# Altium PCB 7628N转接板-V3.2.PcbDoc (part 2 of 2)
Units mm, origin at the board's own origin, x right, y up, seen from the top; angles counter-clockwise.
Board outline 53 x 34 mm, 2 copper layers (Top, Bottom), stack 1.981 mm thick; 6 components, 131 nets, 219 pads, 60 vias.
Unrouted connection lines stored in the file: 5.
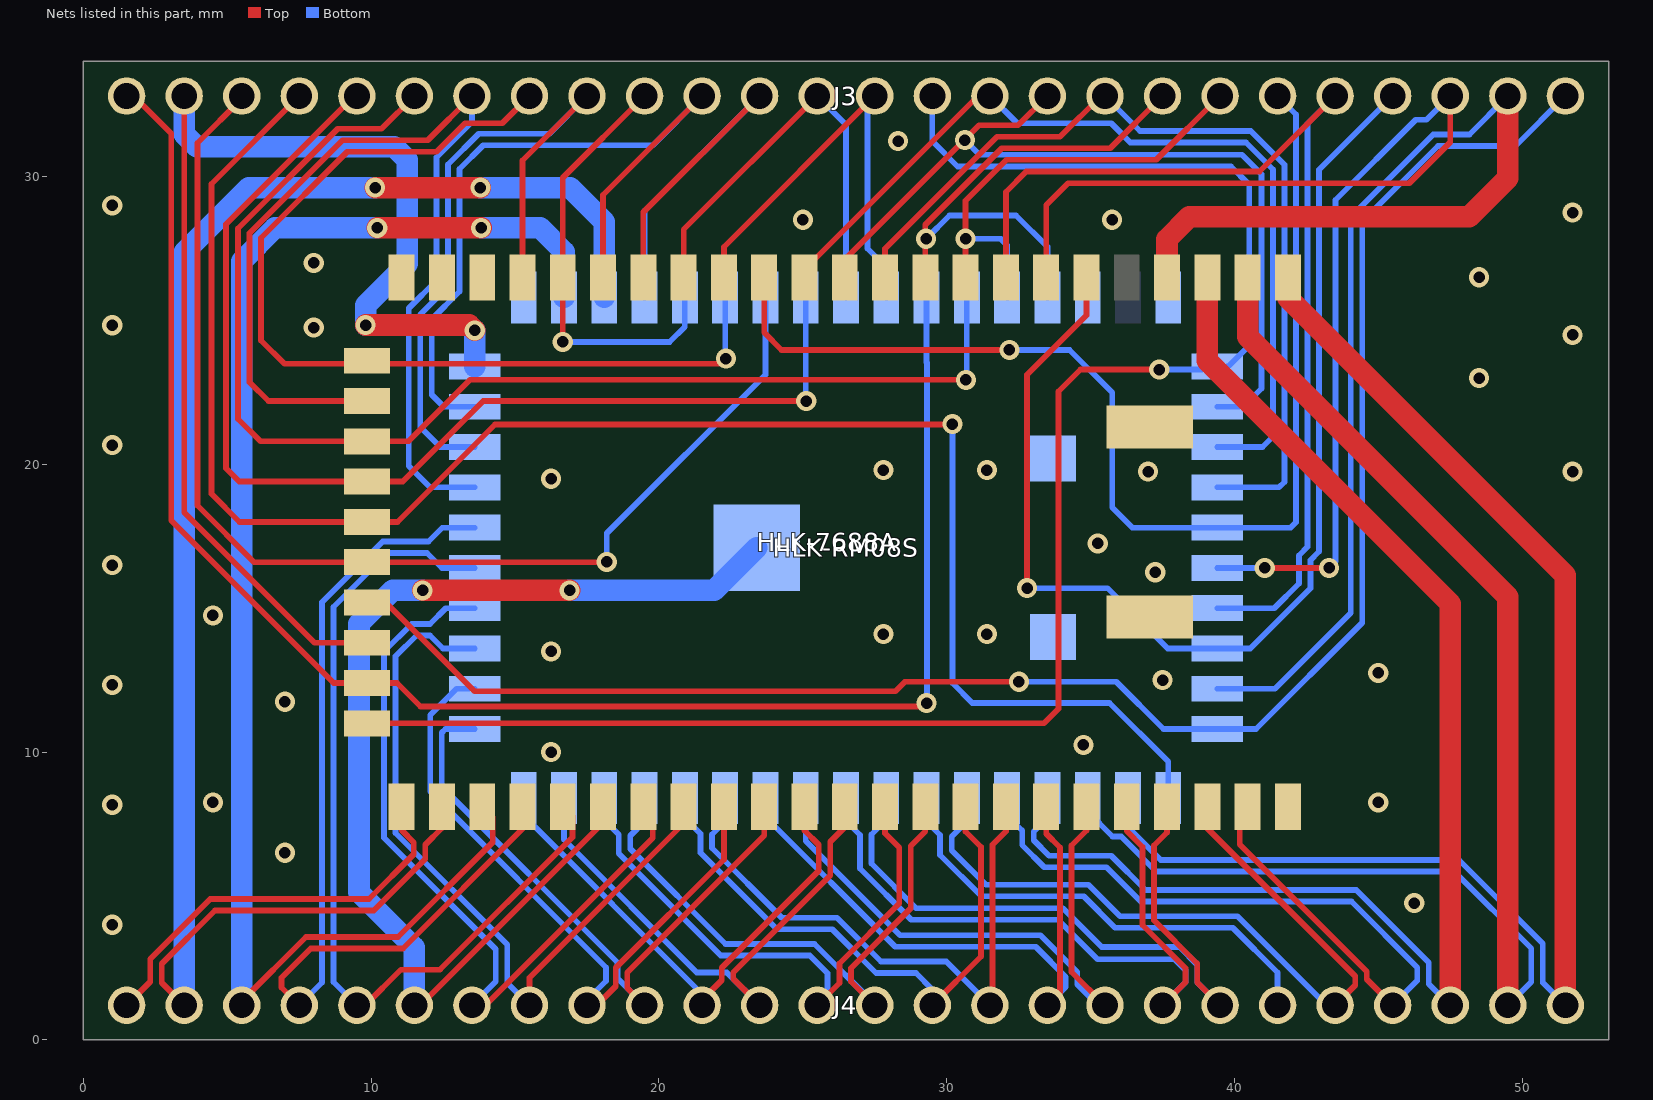
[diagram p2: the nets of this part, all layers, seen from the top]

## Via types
v1: diameter 0.7, hole 0.4, Top to Bottom, tented both sides, 59 vias
v2: diameter 0.7, hole 0.4, Top to Bottom, 1 vias

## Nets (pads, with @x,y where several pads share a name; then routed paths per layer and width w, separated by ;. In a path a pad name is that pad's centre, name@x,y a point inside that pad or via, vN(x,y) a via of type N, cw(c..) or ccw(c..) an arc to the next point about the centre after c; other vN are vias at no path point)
3.3VD: HLK-7688A.2 HLK-7688A.3 HLK-RM08S.39 HLK-RM08S.40 J4.24 J4.25 | length 142.1
  Top w0.75: v1(10.135,29.616) v1(13.792,29.616) ; v1(10.211,28.219) v1(13.818,28.219) ; HLK-7688A.3@39.057,26.499 39.057,23.605 47.5,15.162 J4.24@47.5,1.2 ; HLK-7688A.2@40.457,26.499 40.457,24.44 49.5,15.397 J4.25@49.5,1.2
  Bottom w0.75: J4.25@3.5,1.2 3.5,27.376 5.74,29.616 v1(10.135,29.616) ; J4.24@5.5,1.2 5.5,27.065 6.655,28.219 v1(10.211,28.219) ; v1(13.792,29.616) 16.916,29.616 18.1,28.433 HLK-RM08S.40@18.1,25.8 ; v1(13.818,28.219) 15.875,28.219 16.7,27.394 HLK-RM08S.39@16.7,25.8
$$$1: HLK-7688A.37 HLK-RM08S.15 J4.4 | length 31.5
  Top w0.2: J4.4@7.5,1.2 6.883,1.817 6.883,2.159 7.899,3.175 11.1,3.175 15.257,7.332 HLK-7688A.37@15.257,8.099
  Bottom w0.2: HLK-RM08S.15@32.1,8.4 32.1,7.8 32.621,7.278 32.621,6.77 33.392,6 35.551,6 36.742,4.809 44.064,4.809 46.356,2.516 46.356,2.056 J4.4@45.5,1.2
$$$2: HLK-7688A.36 HLK-RM08S.14 J4.3 | length 31.5
  Top w0.2: J4.3@5.5,1.2 5.5,1.341 7.734,3.575 10.934,3.575 14.224,6.865 14.224,7.732 HLK-7688A.36@13.857,8.099
  Bottom w0.2: HLK-RM08S.14@33.5,8.4 33.5,7.719 33.021,7.241 33.021,6.936 33.557,6.4 35.716,6.4 36.908,5.209 44.23,5.209 46.756,2.682 46.756,1.944 J4.3@47.5,1.2
AGND: HLK-7688A.57 HLK-7688A.58 HLK-RM08S.55 HLK-RM08S.56
  other v1: 1,4 46.25,4.75 7,6.5 1,8.167 4.5,8.25 45,8.25 16.25,10 34.75,10.25 7,11.75 1,12.333 37.5,12.5 45,12.75 16.25,13.5 27.8,14.1 31.4,14.1 4.5,14.75 37.25,16.25 1,16.5 35.25,17.25 16.25,19.5 37,19.75 51.75,19.75 27.8,19.8 31.4,19.8 1,20.667 48.5,23 51.75,24.5 8,24.75 1,24.833 48.5,26.5 8,27 25,28.5 35.75,28.5 51.75,28.75 1,29 28.308,31.234
ALARM_IN: HLK-7688A.13 HLK-RM08S.36 J3.16 | length 28.6
  Top w0.2: HLK-7688A.13@25.057,26.499 25.057,26.774 31.083,32.8 J3.16@31.5,32.8
  Bottom w0.2: HLK-RM08S.36@13.6,22 12.522,22 12.104,22.417 12.104,25.045 13.068,26.008 13.068,30.264 13.895,31.091 19.791,31.091 J3.16@21.5,32.8
ALARM_OUT: HLK-7688A.43 HLK-RM08S.21 J4.10 | length 23.8
  Top w0.2: J4.10@19.5,1.2 18.898,1.802 18.898,2.337 23.657,7.096 HLK-7688A.43@23.657,8.099
  Bottom w0.2: HLK-RM08S.21@23.7,8.4 23.7,7.748 28.214,3.234 33.091,3.234 34.139,2.186 34.139,1.839 J4.10@33.5,1.2
AMCLK: HLK-7688A.6 HLK-RM08S.48 J3.23 | length 25.9
  Top w0.2: 32.791,15.697 32.791,23.114 34.857,25.18 HLK-7688A.6@34.857,26.499
  Bottom w0.2: HLK-RM08S.48@29.3,25.8 29.3,23.546 29.312,23.534 29.312,11.612
ANT: HLK-7688A.22
CLK_N: 
CLK_P: 
CLKN: 
CLKP: 
CPURST_N: HLK-7688A.14 HLK-RM08S.49 J3.21 | length 13.6
  Top w0.2: HLK-7688A.14@23.657,26.499 23.657,24.578 24.257,23.978 v1(32.182,23.978)
  Bottom w0.2: 30.7,22.902 HLK-RM08S.49@30.7,25.8
DDR_BA0: 
DDR_BA1: 
DDR_BA2: 
DDR_CASN: 
DDR_CSN: 
DDR_IO_1V8_MT7688: 
DDR_MCKE: 
DDR_MDQM0: 
DDR_MDQM1: 
DDR_MDQS0: 
DDR_MDQS1: 
DDR_MODT: 
DDR_RASN: 
DDR_VREF: 
DDR_WEN: 
DEFKEY: HLK-7688A.16 HLK-RM08S.47 J3.13 | length 15.6
  Top w0.2: HLK-7688A.16@20.857,26.499 20.857,28.157 J3.13@25.5,32.8
  Bottom w0.2: J3.13@27.5,32.8 27.25,32.55 27.25,27.5 27.9,26.85 HLK-RM08S.47@27.9,25.8
GND: HLK-7688A.1 HLK-7688A.4 HLK-7688A.21 HLK-7688A.23 HLK-7688A.56 HLK-RM08S.37 HLK-RM08S.38 HLK-RM08S.52 HLK-RM08S.54 HLK-RM08S.57 J3.25 J4.21 J4.26 | length 96.1
  Top w0.75: v1(9.804,24.841) 13.411,24.841 v1(13.6,24.652) ; v1(11.786,15.621) v1(16.891,15.621) ; HLK-7688A.4@37.657,26.499 37.657,27.827 38.43,28.6 48.158,28.6 49.5,29.942 J3.25@49.5,32.8 ; HLK-7688A.1@41.857,26.499 41.857,25.783 51.5,16.14 J4.26@51.5,1.2
  Bottom w0.75: J3.25@3.5,32.8 3.5,31.476 3.937,31.039 10.795,31.039 11.252,30.582 11.252,26.975 9.804,25.527 v1(9.804,24.841) ; J4.21@11.5,1.2 11.5,3.207 9.576,5.131 9.576,14.453 10.744,15.621 v1(11.786,15.621) ; HLK-RM08S.37@13.6,23.4 v1(13.6,24.652) ; v1(16.891,15.621) 21.921,15.621 HLK-RM08S.57@23.4,17.1
HOLD: 
I2C_CLK: HLK-7688A.24 HLK-RM08S.51 J3.8 | length 38.2
  Top w0.2: J3.8@15.5,32.8 14.55,31.85 13.257,31.85 12.268,30.861 9.169,30.861 6.172,27.864 6.172,24.308 6.982,23.498 9.857,23.498 22.327,23.498 v1@22.355,23.498
  Bottom w0.2: 29.286,27.838 30.099,28.651 32.41,28.651 33.5,27.562 HLK-RM08S.51@33.5,25.8
  other v1: 22.327,23.673
I2C_DAT: HLK-7688A.25 HLK-RM08S.50 J3.7 | length 22.6
  Top w0.2: HLK-7688A.25@9.857,22.199 6.426,22.199 5.772,22.854 5.772,28.029 9.004,31.261 11.961,31.261 J3.7@13.5,32.8
  Bottom w0.2: 30.657,27.838 31.877,27.838 32.1,27.615 HLK-RM08S.50@32.1,25.8
I2S_CLK: HLK-7688A.20 HLK-RM08S.4 J3.9 | length 27.9
  Top w0.2: HLK-7688A.20@15.257,26.499 15.257,30.557 J3.9@17.5,32.8
  Bottom w0.2: J3.9@35.5,32.8 36.714,31.586 40.566,31.586 41.74,30.413 41.74,19.388 41.552,19.2 HLK-RM08S.4@39.4,19.2
I2S_SDI: HLK-7688A.17 HLK-RM08S.1 J3.12 | length 28.2
  Top w0.2: HLK-7688A.17@19.457,26.499 19.457,28.757 J3.12@23.5,32.8
  Bottom w0.2: J3.12@29.5,32.8 29.5,31.234 30.38,30.355 39.879,30.355 40.514,29.72 40.514,24.132 39.783,23.4 HLK-RM08S.1@39.4,23.4
I2S_SDO: HLK-7688A.18 HLK-RM08S.3 J3.11 | length 30
  Top w0.2: HLK-7688A.18@18.057,26.499 18.057,29.357 J3.11@21.5,32.8
  Bottom w0.2: J3.11@31.5,32.8 32.45,31.85 35.717,31.85 36.381,31.186 40.401,31.186 41.34,30.247 41.34,20.97 40.971,20.6 HLK-RM08S.3@39.4,20.6
I2S_WS: HLK-7688A.19 HLK-RM08S.2 J3.10 | length 29.8
  Top w0.2: v1(16.657,24.252) HLK-7688A.19@16.657,26.499 16.657,29.957 J3.10@19.5,32.8
  Bottom w0.2: v2(30.632,31.267) 31.139,30.761 40.26,30.761 40.94,30.081 40.94,22.633 40.307,22 HLK-RM08S.2@39.4,22
MADDR0: 
MADDR1: 
MADDR2: 
MADDR3: 
MADDR4: 
MADDR5: 
MADDR6: 
MADDR7: 
MADDR8: 
MADDR9: 
MADDR10: 
MADDR11: 
MADDR12: 
MADDR13: 
MDATA0: 
MDATA1: 
MDATA2: 
MDATA3: 
MDATA4: 
MDATA5: 
MDATA6: 
MDATA7: 
MDATA8: 
MDATA9: 
MDATA10: 
MDATA11: 
MDATA12: 
MDATA13: 
MDATA14: 
MDATA15: 
MOTO_D0: HLK-7688A.45 HLK-RM08S.23 J4.12 | length 21.6
  Top w0.2: J4.12@23.5,1.2 22.581,2.119 22.581,2.337 25.952,5.709 25.952,6.883 26.457,7.388 HLK-7688A.45@26.457,8.099
  Bottom w0.2: HLK-RM08S.23@20.9,8.4 20.9,7.71 21.445,7.164 21.445,6.498 24.1,3.843 26.023,3.843 27.547,2.319 28.932,2.319 29.5,1.751 J4.12@29.5,1.2
MOTO_D1: HLK-7688A.39 HLK-RM08S.17 J4.6 | length 26.5
  Top w0.2: J4.6@11.5,1.2 11.716,1.2 18.057,7.541 HLK-7688A.39@18.057,8.099
  Bottom w0.2: HLK-RM08S.17@29.3,8.4 29.3,7.584 29.77,7.114 29.77,6.421 31.205,4.986 34.761,4.986 35.853,3.894 39.942,3.894 41.5,2.337 J4.6@41.5,1.2
MOTO_D2: HLK-7688A.30 HLK-RM08S.11 J3.26 | length 43.2
  Top w0.2: HLK-7688A.30@9.857,15.199 10.505,15.199 13.589,12.116 28.216,12.116 28.546,12.446 v1(32.512,12.446) ; v1@32.512,12.344 v1@32.715,12.344
  Bottom w0.2: 30.2,21.4 30.2,12.4 30.891,11.709 35.662,11.709 37.7,9.671 HLK-RM08S.11@37.7,8.4
MOTO_D3: HLK-7688A.42 HLK-RM08S.20 J4.9 | length 23.6
  Top w0.2: J4.9@17.5,1.2 17.837,1.2 18.498,1.861 18.498,2.502 22.257,6.262 HLK-7688A.42@22.257,8.099
  Bottom w0.2: HLK-RM08S.20@25.1,8.4 25.1,6.914 28.38,3.634 33.257,3.634 34.539,2.352 34.539,1.924 35.263,1.2 J4.9@35.5,1.2
MOTO_D4: HLK-7688A.44 HLK-RM08S.22 J4.11 | length 22.6
  Top w0.2: J4.11@21.5,1.2 21.5,1.39 22.181,2.071 22.181,2.502 25.552,5.874 25.552,6.782 25.057,7.277 HLK-7688A.44@25.057,8.099
  Bottom w0.2: HLK-RM08S.22@22.3,8.4 22.3,7.594 21.845,7.139 21.845,6.663 24.265,4.243 26.189,4.243 27.713,2.719 29.981,2.719 J4.11@31.5,1.2
MOTO_D5: HLK-7688A.8 HLK-RM08S.45 J3.22 | length 19.4
  Top w0.2: HLK-7688A.8@32.057,26.499 32.057,29.466 32.766,30.175 40.875,30.175 J3.22@43.5,32.8
  Bottom w0.2: HLK-RM08S.45@25.1,25.8 25.1,22.22 25.121,22.2
MOTO_D6: HLK-7688A.38 HLK-RM08S.16 J4.5 | length 28.7
  Top w0.2: J4.5@9.5,1.2 9.792,1.2 11.03,2.438 12.388,2.438 16.993,7.043 16.993,7.764 HLK-7688A.38@16.657,8.099
  Bottom w0.2: HLK-RM08S.16@30.7,8.4 30.7,7.586 30.177,7.063 30.177,6.58 31.37,5.386 34.926,5.386 36.019,4.294 40.108,4.294 43.202,1.2 J4.5@43.5,1.2
MOTO_D7: HLK-7688A.41 HLK-RM08S.19 J4.8 | length 26.1
  Top w0.2: J4.8@15.5,1.2 15.5,2.158 20.857,7.515 HLK-7688A.41@20.857,8.099
  Bottom w0.2: HLK-RM08S.19@26.5,8.4 26.5,7.596 26.983,7.114 26.983,5.957 28.766,4.174 33.872,4.174 35.25,2.796 37.924,2.796 38.305,2.415 38.305,2.005 J4.8@37.5,1.2
MOTO_DOWN: HLK-7688A.12 HLK-RM08S.42 J3.17 | length 15.5
  Top w0.2: HLK-7688A.12@26.457,26.499 26.457,27.117 31.121,31.782 32.482,31.782 J3.17@33.5,32.8
  Bottom w0.2: 16.657,24.252 20.371,24.252 20.9,24.781 HLK-RM08S.42@20.9,25.8
MOTO_LEFT: HLK-7688A.10 HLK-RM08S.43 J3.19 | length 14.1
  Top w0.2: HLK-7688A.10@29.257,26.499 29.257,27.838 29.257,28.324 31.915,30.982 35.682,30.982 J3.19@37.5,32.8
  Bottom w0.2: HLK-RM08S.43@22.3,25.8 22.3,23.629 22.329,23.599
  other v1: 29.286,27.838
MOTO_RIGHT: HLK-7688A.11 HLK-RM08S.35 J3.18 | length 28.4
  Top w0.2: HLK-7688A.11@27.857,26.499 27.857,27.49 31.749,31.382 33.94,31.382 35.359,32.8 J3.18@35.5,32.8
  Bottom w0.2: HLK-RM08S.35@13.6,20.6 12.398,20.6 11.704,21.293 11.704,25.21 12.668,26.174 12.668,30.423 13.737,31.491 16.191,31.491 J3.18@17.5,32.8
MOTO_UP: HLK-7688A.9 HLK-RM08S.34 J3.20 | length 29.4
  Top w0.2: HLK-7688A.9@30.657,26.499 v1(30.657,27.838) 30.657,29.158 32.08,30.582 37.282,30.582 J3.20@39.5,32.8
  Bottom w0.2: J3.20@13.5,32.8 13.5,31.9 12.268,30.668 12.268,26.389 11.304,25.425 11.304,19.941 12.045,19.2 HLK-RM08S.34@13.6,19.2
N25649: 
N17083158: 
N17083162: 
N17083174: 
N17083274: 
N17083406: 
N17083412: 
N17415955: 
N17415957: 
N17416113: 
N17416117: 
N17416125: 
N17416142: 
N17416414: 
N17510965: HLK-7688A.50 HLK-RM08S.28 J4.17 | length 20.9
  Top w0.2: HLK-7688A.50@33.457,8.099 33.457,7.164 33.941,6.68 33.941,1.641 J4.17@33.5,1.2
  Bottom w0.2: HLK-RM08S.28@13.6,10.8 12.578,10.8 12.447,10.67 12.447,8.797 18.562,2.682 18.562,2.138 J4.17@19.5,1.2
N17522973: 
N17522975: 
N17544480: 
N18021801: 
N18021821: 
N18021884: 
PERST_N: HLK-7688A.7 HLK-RM08S.44 J3.24 | length 30.5
  Top w0.2: HLK-7688A.7@33.457,26.499 33.457,29.012 34.214,29.769 46.076,29.769 47.5,31.193 J3.24@47.5,32.8
  Bottom w0.2: 18.186,16.612 18.186,17.602 23.7,23.116 HLK-RM08S.44@23.7,25.8
RFOUT_G0_L: 
RXIN0: HLK-7688A.35 HLK-RM08S.13 J4.2 | length 34.7
  Top w0.2: J4.2@3.5,1.2 2.718,1.982 2.718,2.642 4.572,4.496 10.091,4.496 11.881,6.286 11.881,6.782 12.457,7.358 HLK-7688A.35@12.457,8.099
  Bottom w0.2: HLK-RM08S.13@34.9,8.4 34.9,7.927 35.765,7.063 36.063,7.063 37.275,5.85 47.639,5.85 50.319,3.17 50.319,2.019 J4.2@49.5,1.2
RXIP0: HLK-7688A.34 HLK-RM08S.12 J4.1 | length 34
  Top w0.2: J4.1@1.5,1.2 2.318,2.018 2.318,2.807 4.406,4.896 9.925,4.896 11.481,6.452 11.481,6.858 11.057,7.282 HLK-7688A.34@11.057,8.099
  Bottom w0.2: HLK-RM08S.12@36.3,8.4 36.3,7.391 37.441,6.25 47.804,6.25 50.719,3.335 50.719,1.981 J4.1@51.5,1.2
SD_CD: HLK-7688A.47 HLK-RM08S.25 J4.14 | length 20.7
  Top w0.2: J4.14@27.5,1.2 26.67,2.03 26.67,2.489 28.753,4.572 28.753,6.731 29.257,7.235 HLK-7688A.47@29.257,8.099
  Bottom w0.2: HLK-RM08S.25@18.1,8.4 18.1,7.64 18.601,7.139 18.601,6.472 22.144,2.929 25.243,2.929 25.859,2.313 25.859,1.559 J4.14@25.5,1.2
SD_CMD: HLK-7688A.51 HLK-RM08S.29 J4.18 | length 22.7
  Top w0.2: HLK-7688A.51@34.857,8.099 34.857,7.273 34.341,6.756 34.341,2.359 J4.18@35.5,1.2
  Bottom w0.2: HLK-RM08S.29@13.6,12.2 12.962,12.2 12.047,11.286 12.047,8.631 18.162,2.516 18.162,2.043 17.41,1.29 17.32,1.2 J4.18@17.5,1.2
SD_D0: HLK-7688A.49 HLK-RM08S.27 J4.16 | length 16.9
  Top w0.2: J4.16@31.5,1.2 31.591,1.291 31.591,6.782 32.057,7.248 HLK-7688A.49@32.057,8.099
  Bottom w0.2: HLK-RM08S.27@15.3,8.4 15.3,7.792 21.5,1.592 J4.16@21.5,1.2
SD_D1: HLK-7688A.48 HLK-RM08S.26 J4.15 | length 18.4
  Top w0.2: J4.15@29.5,1.2 31.191,2.891 31.191,6.706 30.657,7.24 HLK-7688A.48@30.657,8.099
  Bottom w0.2: HLK-RM08S.26@16.7,8.4 16.7,6.957 21.315,2.342 22.358,2.342 J4.15@23.5,1.2
SD_D2: HLK-7688A.53 HLK-RM08S.31 J4.20 | length 26.1
  Top w0.2: HLK-7688A.53@37.657,8.099 37.657,7.209 37.205,6.756 37.205,4.153 38.703,2.655 38.703,1.997 J4.20@39.5,1.2
  Bottom w0.2: J4.20@13.5,1.2 14.327,2.027 14.327,3.144 10.447,7.024 10.447,13.495 11.406,14.454 12.041,14.454 12.587,15 HLK-RM08S.31@13.6,15
SD_D3: HLK-7688A.52 HLK-RM08S.30 J4.19 | length 25.4
  Top w0.2: HLK-7688A.52@36.257,8.099 36.257,7.253 36.805,6.706 36.805,3.988 38.303,2.489 38.303,2.003 J4.19@37.5,1.2
  Bottom w0.2: HLK-RM08S.30@13.6,13.6 12.495,13.6 12.041,14.054 11.572,14.054 10.847,13.33 10.847,7.19 14.727,3.31 14.727,1.973 J4.19@15.5,1.2
SD_WP: HLK-7688A.46 HLK-RM08S.24 J4.13 | length 21
  Top w0.2: J4.13@25.5,1.2 26.27,1.97 26.27,2.655 28.353,4.738 28.353,6.68 27.857,7.176 HLK-7688A.46@27.857,8.099
  Bottom w0.2: HLK-RM08S.24@19.5,8.4 19.5,7.588 19.001,7.088 19.001,6.638 22.309,3.329 25.408,3.329 27.5,1.237 J4.13@27.5,1.2
SFLASH_CLK: HLK-7688A.27 HLK-RM08S.7 J3.5 | length 57.1
  Top w0.2: J3.5@9.5,32.8 9.407,32.8 4.953,28.346 4.953,19.863 5.416,19.399 HLK-7688A.27@9.857,19.399 11.094,19.399 13.894,22.2 v1(25.121,22.2)
  Bottom w0.2: HLK-RM08S.7@39.4,15 41.384,15 42.24,15.856 42.24,16.835 42.54,17.135 42.54,31.84 J3.5@43.5,32.8
SOC_1.2VD: 
SPI_CLK: 
SPI_CS0: 
SPI_CS1: HLK-7688A.26 HLK-RM08S.5 J3.6 | length 71.2
  Top w0.2: J3.6@11.5,32.8 10.361,31.661 8.838,31.661 5.372,28.195 5.372,21.577 6.15,20.799 HLK-7688A.26@9.857,20.799 11.3,20.799 13.437,22.936 v1(30.666,22.936)
  Bottom w0.2: 32.182,23.978 34.272,23.978 35.75,22.5 35.75,18.5 36.45,17.8 HLK-RM08S.5@39.4,17.8 41.955,17.8 42.14,17.985 42.14,32.16 J3.6@41.5,32.8
SPI_MISO: HLK-7688A.28 HLK-RM08S.8 J3.4 | length 72.5
  Top w0.2: J3.4@7.5,32.8 4.445,29.745 4.445,18.974 5.419,17.999 HLK-7688A.28@9.857,17.999 10.913,17.999 14.3,21.387 30.187,21.387
  Bottom w0.2: v1(32.791,15.697) 35.585,15.697 37.683,13.6 HLK-RM08S.8@39.4,13.6 40.549,13.6 42.64,15.691 42.64,16.669 42.94,16.969 42.94,30.24 J3.4@45.5,32.8
  other v1: 29.3,11.7
SPI_MOSI: HLK-7688A.29 HLK-RM08S.6 J3.3 | length 52.2
  Top w0.2: J3.3@5.5,32.8 5.5,32.703 3.962,31.166 3.962,18.567 5.93,16.599 HLK-7688A.29@9.857,16.599 18.174,16.599 v1(18.186,16.612) ; v1(41.055,16.4) v1(43.29,16.4)
  Bottom w0.2: HLK-RM08S.6@39.4,16.4 v1(41.055,16.4) ; v1(43.29,16.4) 43.51,16.62 43.51,29.185 46.304,31.979 46.679,31.979 J3.3@47.5,32.8
STATUSLED_AU: HLK-7688A.40 HLK-RM08S.18 J4.7 | length 26.9
  Top w0.2: J4.7@13.5,1.2 13.976,1.2 19.787,7.01 19.787,7.77 HLK-7688A.40@19.457,8.099
  Bottom w0.2: HLK-RM08S.18@27.9,8.4 27.9,7.656 27.383,7.139 27.383,6.123 28.932,4.574 34.037,4.574 35.39,3.221 38.089,3.221 38.705,2.606 38.705,1.995 J4.7@39.5,1.2
UART_RXD0: HLK-7688A.32 HLK-RM08S.10 J3.1 | length 81.5
  Top w0.2: J3.1@1.5,32.8 1.744,32.8 3.048,31.496 3.048,18.052 8.701,12.399 HLK-7688A.32@9.857,12.399 10.892,12.399 11.709,11.582 29.182,11.582 29.3,11.7
  Bottom w0.2: 32.512,12.446 35.89,12.446 37.536,10.8 HLK-RM08S.10@39.4,10.8 40.746,10.8 44.444,14.497 44.444,28.435 47.075,31.066 49.766,31.066 J3.1@51.5,32.8
  other v1: 30.2,21.4
UART_TXD0: HLK-7688A.31 HLK-RM08S.9 J3.2 | length 49.4
  Top w0.2: J3.2@3.5,32.8 3.5,18.325 8.026,13.799 HLK-7688A.31@9.857,13.799
  Bottom w0.2: HLK-RM08S.9@39.4,12.2 41.41,12.2 44.044,14.834 44.044,28.6 46.909,31.466 48.166,31.466 J3.2@49.5,32.8
UART_TXD1: HLK-7688A.15 HLK-RM08S.46 J3.14 | length 15.9
  Top w0.2: HLK-7688A.15@22.257,26.499 22.257,27.557 J3.14@27.5,32.8
  Bottom w0.2: J3.14@25.5,32.8 26.5,31.8 HLK-RM08S.46@26.5,25.8
USB_DN: HLK-7688A.55 HLK-RM08S.33 J4.23 | length 29.9
  Top w0.2: HLK-7688A.55@40.457,8.099 40.183,7.825 40.183,6.789 44.596,2.375 44.596,2.104 J4.23@45.5,1.2
  Bottom w0.2: J4.23@7.5,1.2 8.288,1.988 8.288,15.204 10.402,17.318 11.99,17.318 12.472,17.8 HLK-RM08S.33@13.6,17.8
USB_DP: HLK-7688A.54 HLK-RM08S.32 J4.22 | length 29.4
  Top w0.2: HLK-7688A.54@39.057,8.099 39.057,7.349 44.196,2.21 44.196,1.896 J4.22@43.5,1.2
  Bottom w0.2: J4.22@9.5,1.2 8.688,2.012 8.688,15.038 10.568,16.918 11.939,16.918 12.457,16.4 HLK-RM08S.32@13.6,16.4
WF0_IPA: 
WF1_2GPA_3V3_IN: 
WF1_IPA: 
WF_SX_3V3_IN: 
WLED_N: HLK-7688A.33 HLK-RM08S.41 J3.15 | length 49.6
  Top w0.2: HLK-7688A.33@9.857,10.999 33.377,10.999 33.884,11.506 33.884,22.53 34.646,23.292 v1(37.389,23.292)
  Bottom w0.2: HLK-RM08S.41@19.5,25.8 19.5,28.8 J3.15@23.5,32.8 ; v1(37.389,23.292) 39.292,23.292
WP: 
XIN: 
pads on no net: HLK-7688A.5 HLK-RM08S.53

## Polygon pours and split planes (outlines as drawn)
AGND on Top "Top Overlay-No Net" (solid, pour order 6): 0,0 53,0 53,34 0,34
GND on Mid-Layer 1 "Mid-Layer 1-GND" (solid, remove dead copper, pour order 4): -1.975,34.054 54.93,34.054 54.93,0.038 -1.975,0.038
AGND on Bottom "Top Overlay-No Net" (solid, pour order 5): 0,0 53,0 53,34 0,34

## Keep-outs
Keep-Out Layer:
  the board outline again, w0.127

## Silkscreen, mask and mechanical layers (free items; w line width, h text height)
Silkscreen Top:
  lines w0.1: 43.188,7.942 45,7.942 45,26.641 43.188,26.641 ; 45.4,21.5 49.7,21.5 49.7,12.4 45.5,12.4 ; 47.6,12.4 47.7,12.4 47.7,21.5
  lines w0.102: 0.488,0.184 0.488,2.196 52.499,2.196 52.499,0.184 0.488,0.184 ; 0.498,31.801 0.498,33.813 52.508,33.813 52.508,31.801 0.498,31.801
  lines w0.12: 10.414,3.556 15.748,3.556 ; 16.129,3.556 21.463,3.556 ; 21.844,3.556 26.924,3.556 ; 27.432,3.556 32.512,3.556 ; 33.02,3.556 38.1,3.556 ; 37.338,30.226 42.672,30.226
  text "POWER" at 38.354,30.607 h0.7
  text "52" at 2,30 h0.85 r90
  text "27" at 52,30 h0.85 r90
  text "GND" at 11.5,27.8 h0.7 r90
  text "ANT" at 12.9,27.8 h0.7 r90
  text "GND" at 14.3,27.8 h0.7 r90
  text "I2S_CLK" at 15.7,27.8 h0.7 r90
  text "I2S_WS" at 17.1,27.8 h0.7 r90
  text "I2S_DO" at 18.5,27.8 h0.7 r90
  text "I2S_DI" at 19.9,27.8 h0.7 r90
  text "RXD1" at 21.3,27.8 h0.7 r90
  text "TXD1" at 22.7,27.8 h0.7 r90
  text "PORST" at 24.1,27.8 h0.7 r90
  text "E_LED0" at 25.5,27.8 h0.7 r90
  text "E_LED1" at 26.9,27.8 h0.7 r90
  text "E_LED2" at 28.3,27.8 h0.7 r90
  text "E_LED3" at 29.7,27.8 h0.7 r90
  text "E_LED4" at 31.1,27.8 h0.7 r90
  text "WDTRST" at 32.5,27.8 h0.7 r90
  text "PERST" at 33.9,27.8 h0.7 r90
  text "RCLK0" at 35.3,27.8 h0.7 r90
  text "SPICS0" at 36.7,27.8 h0.7 r90
  text "GND" at 38.1,27.8 h0.7 r90
  text "3.3V" at 39.5,27.8 h0.7 r90
  text "3.3V" at 40.9,27.8 h0.7 r90
  text "GND" at 42.3,27.8 h0.7 r90
  text "23" at 10,27.1 h0.85 r90
  text "I2C_CLK" at 4.9,23.3 h0.7
  text "I2C_SD" at 5.45,21.9 h0.7
  text "SPI_CS1" at 5.127,20.5 h0.7
  text "SPI_CLK" at 4.973,19.1 h0.7
  text "SPI_MISO" at 4.577,17.7 h0.7
  text "SPI_MOSI" at 4.56,16.3 h0.7
  text "GPIO0" at 6.036,14.9 h0.7
  text "UART_TXD0" at 3.214,13.5 h0.7
  text "HLK-7628N" at 49.2,13 h1 r90
  text "UART_RXD0" at 3.14,12.1 h0.7
  text "WLED_N" at 5.083,10.7 h0.7
  text "34" at 10,6.2 h0.85 r90
  text "56" at 43.7,6.2 h0.85 r90
  text "HLK-7688A/7628N-KIT-V3.2" at 2.4,5.8 h1.1 r90
  text "GND" at 42.2,5.1 h0.7 r90
  text "P1_TP" at 17,4.11 h0.7 r90
  text "P1_TN" at 18.4,4.11 h0.7 r90
  text "P1_RP" at 19.8,4.037 h0.7 r90
  text "P1_RN" at 21.2,4.037 h0.7 r90
  text "P0_TP" at 14.2,4 h0.7 r90
  text "P0_TN" at 15.6,4 h0.7 r90
  text "P2_TP" at 25.4,4 h0.7 r90
  text "P2_TN" at 26.8,4 h0.7 r90
  text "P3_TP" at 28.2,4 h0.7 r90
  text "P3_TN" at 29.6,4 h0.7 r90
  text "P4_TP" at 36.6,4 h0.7 r90
  text "P4_TN" at 38,4 h0.7 r90
  text "P0_RP" at 11.4,3.927 h0.7 r90
  text "P0_RN" at 12.8,3.927 h0.7 r90
  text "P2_RP" at 22.6,3.927 h0.7 r90
  text "P2_RN" at 24,3.927 h0.7 r90
  text "P3_RP" at 31,3.927 h0.7 r90
  text "P3_RN" at 32.4,3.927 h0.7 r90
  text "P4_RP" at 33.8,3.927 h0.7 r90
  text "P4_RN" at 35.2,3.927 h0.7 r90
  text "USB_DP" at 39.4,3.267 h0.7 r90
  text "USB_DM" at 40.8,3.2 h0.7 r90
  text "1" at 2,2.75 h0.85 r90
  text "WAN" at 12.065,2.54 h0.7
  text "LAN1" at 17.78,2.54 h0.7
  text "LAN2" at 23.495,2.54 h0.7
  text "LAN3" at 29.083,2.54 h0.7
  text "LAN4" at 34.671,2.54 h0.7
  text "26" at 52,2.5 h0.85 r90
Silkscreen Bottom:
  lines w0.102: 0.492,31.801 52.502,31.801 52.502,33.813 0.492,33.813 0.492,31.801 ; 0.501,0.184 52.512,0.184 52.512,2.196 0.501,2.196 0.501,0.184
  lines w0.12: 8.636,10.033 8.636,15.367 ; 14.732,3.683 19.939,3.683 ; 20.447,3.683 25.527,3.683 ; 25.908,29.591 28.321,29.591 ; 26.035,3.683 31.242,3.683 ; 31.623,3.683 36.957,3.683 ; 46.863,10.287 46.863,12.573 ; 4.445,12.192 6.477,12.192 6.477,21.463 4.445,21.463 4.445,12.192
  text "27" at 1,30.1 h0.85 r270
  text "52" at 51.1,30.1 h0.85 r270
  text "UART1" at 28.448,29.972 h0.7
  text "GND" at 14.9,27.2 h0.7 r270
  text "3.3V" at 16.3,27.2 h0.7 r270
  text "3.3V" at 17.7,27.2 h0.7 r270
  text "WLED_N" at 19.1,27.2 h0.7 r270
  text "E_LED1" at 20.5,27.2 h0.7 r270
  text "E_LED3" at 21.9,27.2 h0.7 r270
  text "PERST_N" at 23.3,27.2 h0.7 r270
  text "WDT_RST" at 24.7,27.2 h0.7 r270
  text "TXD1" at 26.1,27.2 h0.7 r270
  text "RXD1" at 27.5,27.2 h0.7 r270
  text "REFCLK0" at 28.9,27.2 h0.7 r270
  text "PORST_N" at 30.3,27.2 h0.7 r270
  text "I2C_SD" at 31.7,27.2 h0.7 r270
  text "I2C_CLK" at 33.1,27.2 h0.7 r270
  text "GND" at 34.5,27.2 h0.7 r270
  text "ANT" at 35.9,27.2 h0.7 r270
  text "GND" at 37.3,27.2 h0.7 r270
  text "54" at 38.7,26.3 h0.85 r270
  text "38" at 13.4,26.2 h0.85 r270
  text "GND" at 12.1,23 h0.7
  text "I2S_DI" at 43.551,23 h0.7
  text "E_LED0" at 12.1,21.796 h0.7
  text "I2S_WS" at 44.2,21.6 h0.7
  text "E_LED2" at 12.1,20.359 h0.7
  text "I2S_DO" at 44.084,20.2 h0.7
  text "E_LED4" at 12.1,18.922 h0.7
  text "I2S_CLK" at 44.567,18.8 h0.7
  text "USB_DM" at 12.1,17.485 h0.7
  text "SPI_CS1" at 44.414,17.4 h0.7
  text "USB_DP" at 12.1,16.048 h0.7
  text "SPI_MOSI" at 44.98,16 h0.7
  text "P4_TN" at 12.1,14.611 h0.7
  text "SPI_CLK" at 44.567,14.6 h0.7
  text "SPI_MISO" at 44.964,13.2 h0.7
  text "P4_TP" at 12.1,13.174 h0.7
  text "UART_TXD0" at 46.327,11.8 h0.7
  text "P4_RN" at 12.1,11.737 h0.7
  text "LAN4" at 7.62,11.684 h0.7 r270
  text "UART_RXD0" at 46.4,10.4 h0.7
  text "P4_RP" at 12.1,10.3 h0.7
  text "UART0" at 47.244,10.033 h0.7 r270
  text "HLK-RM08S-KIT-V3.2" at 49.7,8.9 h1.2 r270
  text "11" at 38.7,7 h0.85 r270
  text "27" at 13.4,6.6 h0.85 r270
  text "GPIO0" at 37.3,4.4 h0.7 r270
  text "P1_TN" at 29.046,4.217 h0.7 r270
  text "P1_TP" at 30.46,4.217 h0.7 r270
  text "T0_TN" at 31.875,4.18 h0.7 r270
  text "P1_RN" at 26.217,4.143 h0.7 r270
  text "P1_RP" at 27.631,4.143 h0.7 r270
  text "P3_TN" at 17.729,4.107 h0.7 r270
  text "P3_TP" at 19.144,4.107 h0.7 r270
  text "P2_TN" at 20.558,4.107 h0.7 r270
  text "P2_TP" at 21.973,4.107 h0.7 r270
  text "P0_TP" at 33.29,4.107 h0.7 r270
  text "P3_RN" at 14.9,4.033 h0.7 r270
  text "P3_RP" at 16.315,4.033 h0.7 r270
  text "P2_RN" at 23.387,4.033 h0.7 r270
  text "P2_RP" at 24.802,4.033 h0.7 r270
  text "P0_RN" at 34.704,4.033 h0.7 r270
  text "P0_RP" at 36.119,4.033 h0.7 r270
  text "1" at 51,2.8 h0.85 r270
  text "26" at 1,2.7 h0.85 r270
  text "LAN3" at 18.288,2.667 h0.7
  text "LAN2" at 24.003,2.667 h0.7
  text "LAN1" at 29.591,2.667 h0.7
  text "WAN" at 35.306,2.667 h0.7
